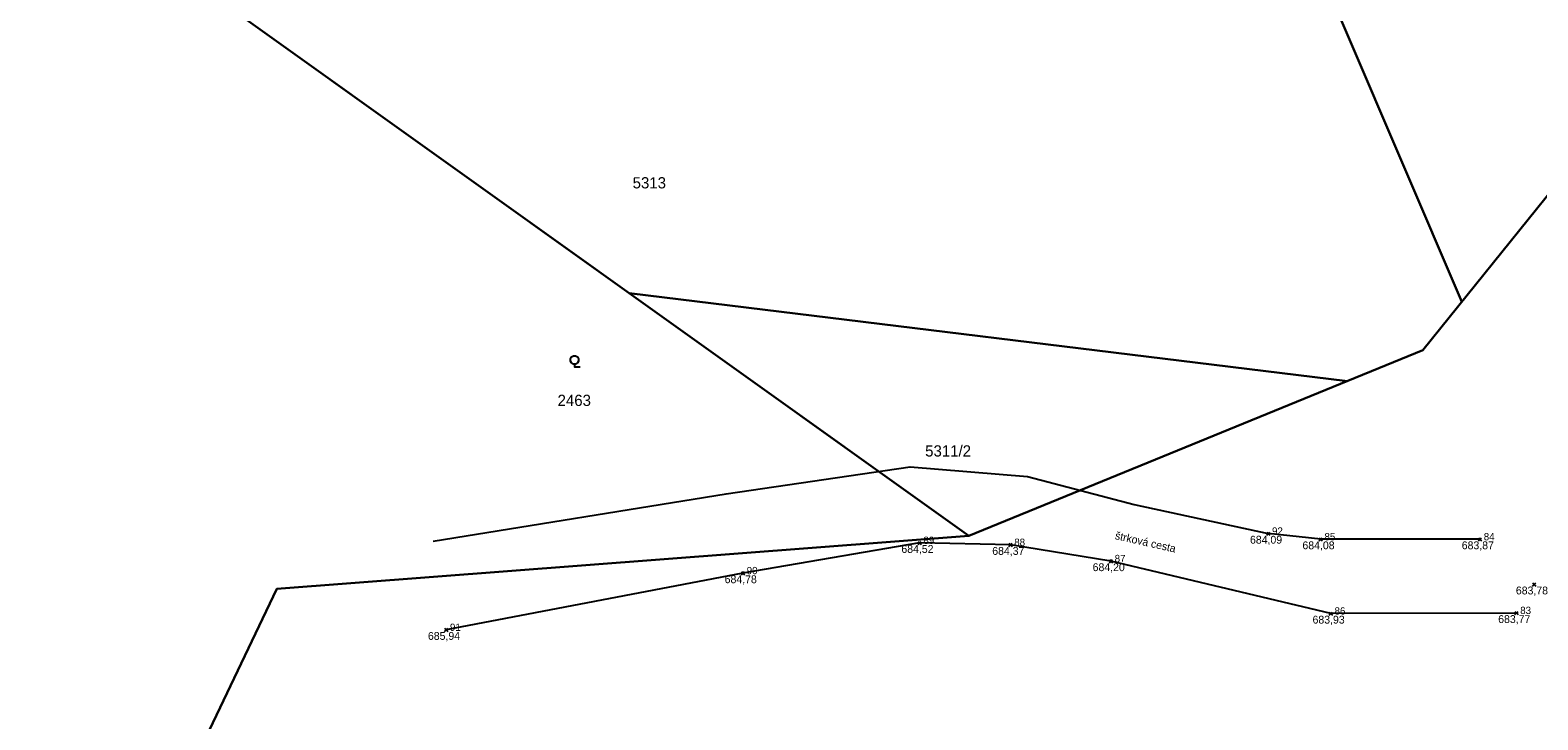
# Model space of a CAD drawing. Extents: x -439750 to -439180, y -1258684 to -1258308.
# Drawn here: x -439598.2 to -439544.4, y -1258510.9 to -1258486.3 of the extents above; entities that cross this region are included whole.
import ezdxf

# ---------------------------------------------------------------- set-up
doc = ezdxf.new("R2010")
doc.units = 0
for name, color, linetype in [('BODY', 7, 'Continuous'), ('CISBOD', 7, 'Continuous'), ('KATASTER', 7, 'Continuous'), ('POLOHOPIS', 7, 'Continuous'), ('UOV', 7, 'Continuous'), ('VYSKY', 7, 'Continuous')]:
    doc.layers.add(name, color=color, linetype=linetype)

# ---------------------------------------------------------------- blocks, each defined once
blk = doc.blocks.new('305')
blk.add_lwpolyline([(0, 0.53), (-0.19, 0.53), (-0.53, 0.72), (-0.72, 1.06), (-0.72, 1.45), (-0.53, 1.79), (-0.19, 1.98), (0.2, 1.98), (0.54, 1.79), (0.73, 1.45), (0.73, 1.06), (0.54, 0.72), (0.2, 0.53), (0.01, 0.53), (0.01, 0), (1.01, 0)])
blk = doc.blocks.new('KRIZEK')
for p, q in [((-2, 0), (2, 0)), ((0, 2), (0, -2))]:
    blk.add_line(p, q)

msp = doc.modelspace()

# ---------------------------------------------------------------- linework, layer by layer
at = {"layer": 'KATASTER'}
for points in [[(-439538.17, -1258484.88), (-439548.5, -1258497.7), (-439564.69, -1258504.32), (-439591.03, -1258485.49), (-439586.03, -1258484.5), (-439585.97, -1258485.58), (-439565.52, -1258484.37), (-439562.93, -1258482.9), (-439556.83, -1258476.59), (-439555.63, -1258473.42), (-439551.33, -1258468.47), (-439546.64, -1258459.47), (-439541.07, -1258454.21)], [(-439548.5, -1258497.7), (-439538.17, -1258484.88), (-439520.19, -1258486.95), (-439507.21, -1258497.49), (-439484.47, -1258496.42), (-439400.54, -1258499.28), (-439387.09, -1258499.74), (-439411.19, -1258562.66), (-439413.56, -1258566.65), (-439437.77, -1258626.82), (-439438.12, -1258627.38), (-439482.75, -1258611.76), (-439518.67, -1258591.95), (-439550.54, -1258581.84), (-439567.51, -1258574.36), (-439597.45, -1258561.13)], [(-439597.45, -1258561.13), (-439597.08, -1258522.38), (-439589.36, -1258506.21), (-439564.69, -1258504.32), (-439548.5, -1258497.7)]]:
    msp.add_lwpolyline(points, dxfattribs=at)
msp.add_lwpolyline([(-439658.88, -1258489.54), (-439635.72, -1258471.93), (-439620.34, -1258480.81), (-439606.15, -1258484.83), (-439591.03, -1258485.49), (-439564.69, -1258504.32), (-439589.36, -1258506.21), (-439597.08, -1258522.38), (-439597.45, -1258561.13), (-439640.46, -1258538.63)], close=True, dxfattribs=at)
at = {"layer": 'POLOHOPIS'}
for points in [[(-439583.79, -1258504.51), (-439573.34, -1258502.82), (-439566.78, -1258501.86), (-439562.59, -1258502.2), (-439558.79, -1258503.2), (-439554.01, -1258504.24)], [(-439546.46, -1258504.44), (-439552.14, -1258504.44), (-439554.01, -1258504.24)], [(-439545.16, -1258507.07), (-439551.78, -1258507.09), (-439559.62, -1258505.22), (-439563.2, -1258504.64), (-439566.44, -1258504.57), (-439572.74, -1258505.65), (-439583.32, -1258507.67)]]:
    msp.add_lwpolyline(points, dxfattribs=at)
at = {"layer": 'UOV'}
for points in [[(-439520.19, -1258486.95), (-439538.17, -1258484.88), (-439547.11, -1258495.98), (-439553.31, -1258481.48), (-439550.29, -1258478.38), (-439548.77, -1258475.54), (-439547.7, -1258471.18), (-439548.42, -1258468.53), (-439551.33, -1258468.47), (-439546.64, -1258459.47), (-439541.07, -1258454.21), (-439536.69, -1258451.87), (-439531.73, -1258450.85), (-439525.5, -1258450.78), (-439520.66, -1258452.66), (-439516.51, -1258455.4), (-439512.86, -1258458.3), (-439509.68, -1258462.08), (-439514.85, -1258480.71), (-439512.85, -1258480.94), (-439510.04, -1258487.61), (-439512.62, -1258492.23), (-439513.68, -1258492.23)], [(-439565.52, -1258484.37), (-439562.93, -1258482.9), (-439562.47, -1258482.43), (-439553.31, -1258481.48), (-439547.11, -1258495.98), (-439548.5, -1258497.7), (-439551.19, -1258498.8), (-439576.8, -1258495.66), (-439591.03, -1258485.49), (-439586.03, -1258484.5), (-439585.97, -1258485.58)], [(-439564.69, -1258504.32), (-439576.8, -1258495.66), (-439551.19, -1258498.8)]]:
    msp.add_lwpolyline(points, close=True, dxfattribs=at)

# ---------------------------------------------------------------- block references
at = {"layer": 'BODY', "xscale": 0.04, "yscale": 0.04000000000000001, "rotation": 44.977187}
for p in [(-439566.44, -1258504.57), (-439563.2, -1258504.64), (-439554.01, -1258504.24), (-439552.14, -1258504.44), (-439546.46, -1258504.44), (-439572.74, -1258505.65), (-439559.62, -1258505.22), (-439544.53, -1258506.05), (-439551.78, -1258507.09), (-439545.16, -1258507.07), (-439583.32, -1258507.67)]:
    msp.add_blockref('KRIZEK', p, dxfattribs=at)
at = {"layer": 'KATASTER', "xscale": 0.2, "yscale": 0.20000000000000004}
msp.add_blockref('305', (-439578.748, -1258498.297), dxfattribs=at)

# ---------------------------------------------------------------- texts
at = {"layer": 'CISBOD'}
for s, p in [('89', (-439566.307, -1258504.606)), ('88', (-439563.067, -1258504.676)), ('92', (-439553.877, -1258504.276)), ('85', (-439552.007, -1258504.476)), ('84', (-439546.327, -1258504.476)), ('87', (-439559.487, -1258505.256)), ('90', (-439572.607, -1258505.686)), ('86', (-439551.647, -1258507.126)), ('83', (-439545.027, -1258507.106)), ('91', (-439583.187, -1258507.706))]:
    msp.add_text(s, height=0.26, dxfattribs=at).set_placement(p)
at = {"layer": 'KATASTER'}
msp.add_text('2463', height=0.4, dxfattribs=at).set_placement((-439579.35, -1258499.687))
at = {"layer": 'POLOHOPIS'}
msp.add_text('štrková cesta', height=0.28, rotation=347.327, dxfattribs=at).set_placement((-439559.493, -1258504.431))
at = {"layer": 'UOV'}
for s, p in [('5313', (-439576.674, -1258491.93)), ('5311/2', (-439566.244, -1258501.49))]:
    msp.add_text(s, height=0.4, dxfattribs=at).set_placement(p)
at = {"layer": 'VYSKY'}
for s, p in [('684,09', (-439554.662, -1258504.596)), ('684,08', (-439552.792, -1258504.796)), ('683,87', (-439547.112, -1258504.796)), ('684,52', (-439567.092, -1258504.926)), ('684,37', (-439563.852, -1258504.996)), ('684,20', (-439560.272, -1258505.576)), ('684,78', (-439573.392, -1258506.006)), ('683,78', (-439545.182, -1258506.406)), ('683,93', (-439552.432, -1258507.446)), ('683,77', (-439545.812, -1258507.426)), ('685,94', (-439583.972, -1258508.026))]:
    msp.add_text(s, height=0.28, dxfattribs=at).set_placement(p)

doc.saveas('drawing.dxf')
